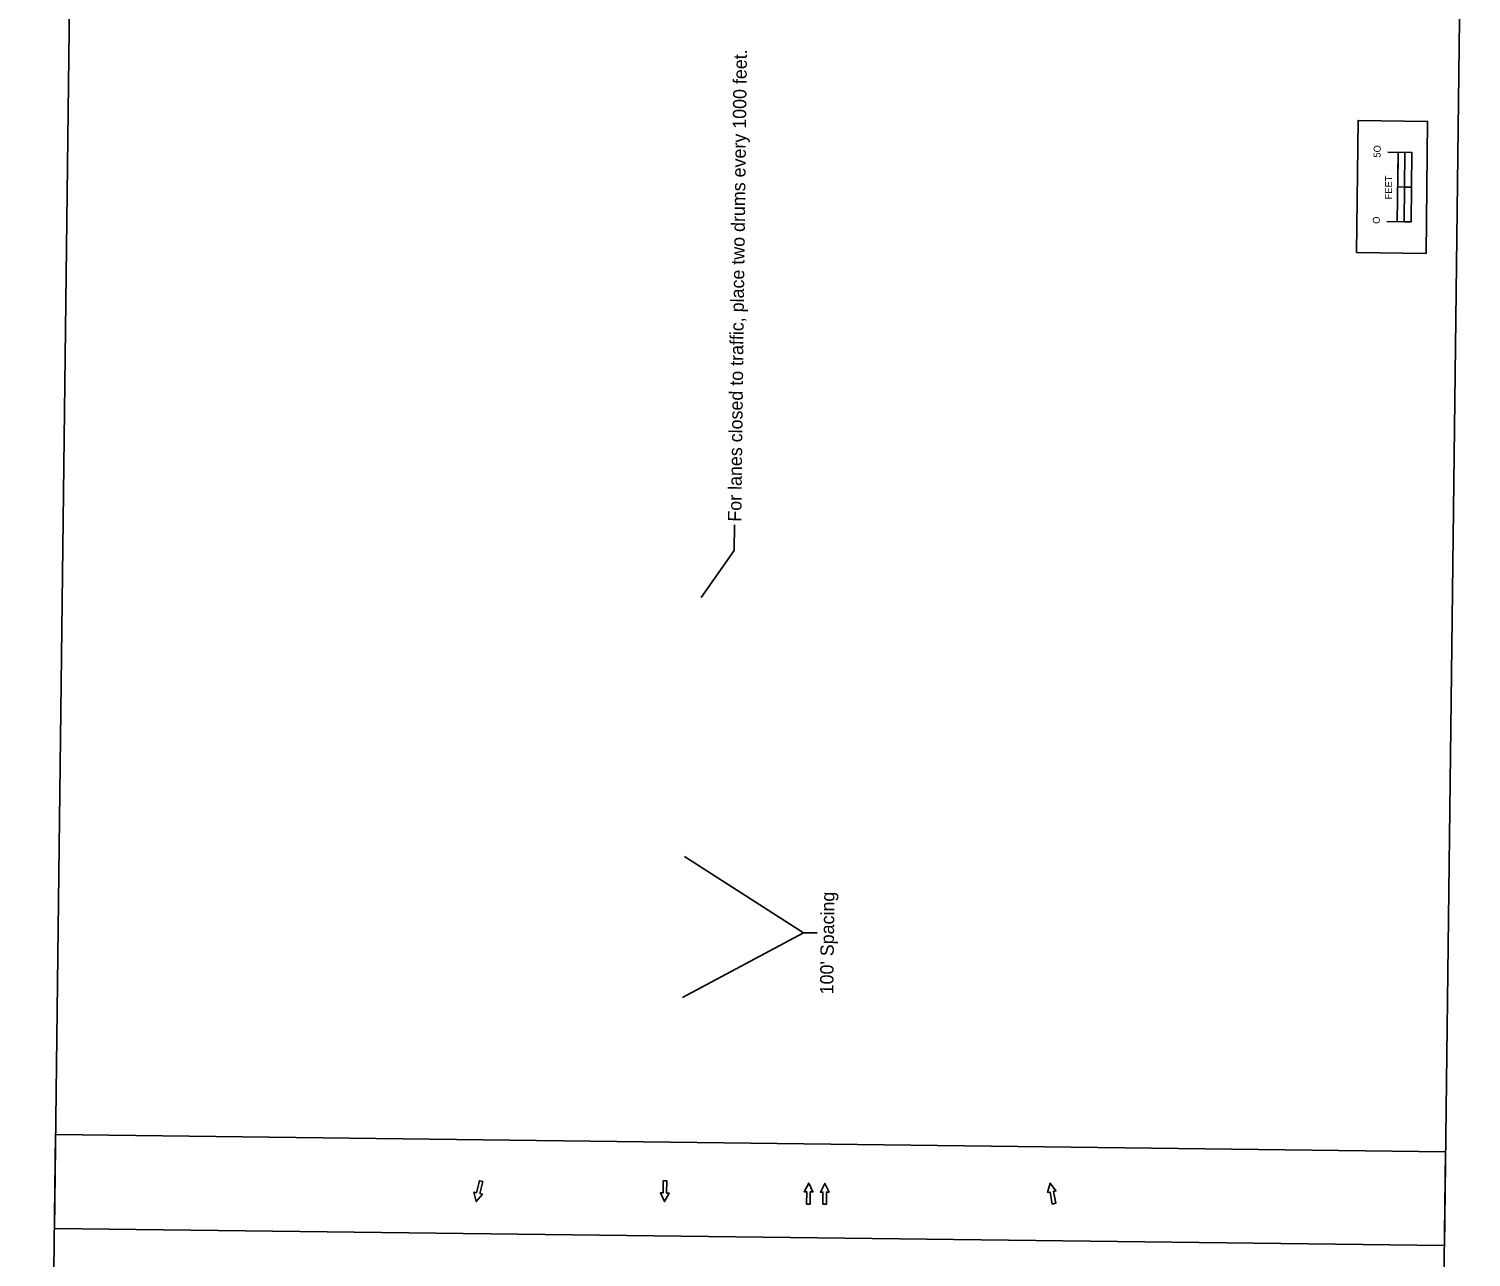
# Model space of a CAD drawing. Extents: x 4959127 to 4960275, y 3872379 to 3884458.
# Drawn here: x 4959219 to 4960256, y 3881370 to 3882253 of the extents above; entities that cross this region are included whole.
import ezdxf

# ---------------------------------------------------------------- set-up
doc = ezdxf.new("R2010")
doc.units = 0
for name, color, linetype in [('dsnCellElements', 7, 'Continuous'), ('dsnCellsScaleBlock', 7, 'Continuous'), ('Level 2', 7, 'Continuous'), ('Level 5', 7, 'Continuous'), ('NamedBoundary', 7, 'Continuous'), ('SheetText', 7, 'Continuous')]:
    doc.layers.add(name, color=color, linetype=linetype)

msp = doc.modelspace()

# ---------------------------------------------------------------- linework, layer by layer
at = {"layer": 'dsnCellElements'}
msp.add_lwpolyline([(4960173.9, 3882092.6), (4960175, 3882187.6), (4960225, 3882186.9), (4960223.9, 3882091.9)], close=True, dxfattribs=at)
msp.add_lwpolyline([(4960173.9, 3882092.6), (4960175, 3882187.6), (4960225, 3882186.9), (4960223.9, 3882091.9)], close=True, dxfattribs=at)
at = {"layer": 'dsnCellsScaleBlock'}
msp.add_line((4960213.5, 3882139.6), (4960203.5, 3882139.7), dxfattribs=at)
msp.add_line((4960213.5, 3882139.6), (4960203.5, 3882139.7), dxfattribs=at)
for points in [[(4960223.9, 3882091.9), (4960173.9, 3882092.6), (4960175, 3882187.6), (4960225, 3882186.9)], [(4960208.4, 3882139.6), (4960208.7, 3882164.6), (4960203.8, 3882164.7), (4960203.5, 3882139.7)], [(4960213.1, 3882114.6), (4960213.5, 3882139.6), (4960208.4, 3882139.6), (4960208.1, 3882114.6)]]:
    msp.add_lwpolyline(points, close=True, dxfattribs=at)
for points in [[(4960195.6, 3882114.8), (4960213.1, 3882114.6), (4960213.8, 3882164.6), (4960196.3, 3882164.8)], [(4960203.1, 3882114.7), (4960203.8, 3882164.7)]]:
    msp.add_lwpolyline(points, dxfattribs=at)
at = {"layer": 'Level 2'}
for points in [[(4959542.9, 3881425.1), (4959545.3, 3881424.5), (4959543.3, 3881416), (4959545.1, 3881415.5), (4959540.7, 3881410.2), (4959539, 3881417), (4959540.9, 3881416.5)], [(4959675.2, 3881425.1), (4959677.7, 3881425.1), (4959677.6, 3881416.3), (4959679.4, 3881416.3), (4959676.2, 3881410.1), (4959673.2, 3881416.4), (4959675.1, 3881416.4)], [(4959780.8, 3881408.4), (4959778.3, 3881408.4), (4959778.4, 3881417.2), (4959776.6, 3881417.2), (4959779.8, 3881423.4), (4959782.8, 3881417.1), (4959780.9, 3881417.1)], [(4959792.5, 3881408.2), (4959790, 3881408.3), (4959790.1, 3881417), (4959788.3, 3881417), (4959791.5, 3881423.2), (4959794.5, 3881417), (4959792.6, 3881417)], [(4959957.5, 3881408.9), (4959955, 3881408.4), (4959953.4, 3881417), (4959951.6, 3881416.7), (4959953.5, 3881423.4), (4959957.7, 3881417.8), (4959955.9, 3881417.5)]]:
    msp.add_lwpolyline(points, close=True, dxfattribs=at)
at = {"layer": 'Level 5'}
for points in [[(4959540.9, 3881416.5), (4959539, 3881417), (4959540.7, 3881410.2), (4959545.1, 3881415.5), (4959543.3, 3881416), (4959545.3, 3881424.5), (4959542.9, 3881425.1), (4959540.9, 3881416.5)], [(4959675.1, 3881416.4), (4959673.2, 3881416.4), (4959676.2, 3881410.1), (4959679.4, 3881416.3), (4959677.6, 3881416.3), (4959677.7, 3881425.1), (4959675.2, 3881425.1), (4959675.1, 3881416.4)], [(4959780.9, 3881417.1), (4959782.8, 3881417.1), (4959779.8, 3881423.4), (4959776.6, 3881417.2), (4959778.4, 3881417.2), (4959778.3, 3881408.4), (4959780.8, 3881408.4), (4959780.9, 3881417.1)], [(4959792.6, 3881417), (4959794.5, 3881417), (4959791.5, 3881423.2), (4959788.3, 3881417), (4959790.1, 3881417), (4959790, 3881408.3), (4959792.5, 3881408.2), (4959792.6, 3881417)], [(4959955.9, 3881417.5), (4959957.7, 3881417.8), (4959953.5, 3881423.4), (4959951.6, 3881416.7), (4959953.4, 3881417), (4959955, 3881408.4), (4959957.5, 3881408.9), (4959955.9, 3881417.5)]]:
    msp.add_lwpolyline(points, dxfattribs=at)
at = {"layer": 'NamedBoundary'}
for points in [[(4959237.2, 3881390.8), (4960237.1, 3881378.5), (4960256.4, 3882945.9), (4959256.4, 3882958.1)], [(4959218.8, 3879890.9), (4960218.7, 3879878.6), (4960238, 3881446), (4959238, 3881458.3)]]:
    msp.add_lwpolyline(points, close=True, dxfattribs=at)
at = {"layer": 'SheetText'}
msp.add_line((4959776, 3881603.5), (4959690.4, 3881658.3), dxfattribs=at)
for points in [[(4959726.4, 3881896.7), (4959726.2, 3881878.4), (4959702.4, 3881844.6)], [(4959786, 3881603.4), (4959776, 3881603.5), (4959689, 3881556.9)]]:
    msp.add_lwpolyline(points, dxfattribs=at)

# ---------------------------------------------------------------- texts
at = {"layer": 'dsnCellsScaleBlock'}
for s, p in [('5O', (4960191.2, 3882160.8)), ('FEET', (4960199.3, 3882130.8)), ('O', (4960190.6, 3882113.2))]:
    msp.add_text(s, height=5, rotation=89.2975, dxfattribs=at).set_placement(p)
at = {"layer": 'SheetText'}
for s, p in [('For lanes closed to traffic, place two drums every 1000 feet.', (4959731.3, 3881899)), ("100' Spacing", (4959797.5, 3881559.1))]:
    msp.add_text(s, height=9.6, rotation=89.3042, dxfattribs=at).set_placement(p)

doc.saveas('drawing.dxf')
